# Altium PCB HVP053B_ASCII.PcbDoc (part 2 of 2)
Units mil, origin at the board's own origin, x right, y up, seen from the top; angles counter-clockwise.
Board outline 3600 x 3000 mil, 4 copper layers (Top Layer, Signal Layer 1, Signal Layer 2, Bottom Layer), stack 39.6 mil thick; 143 components, 62 nets, 279 pads, 97 vias.
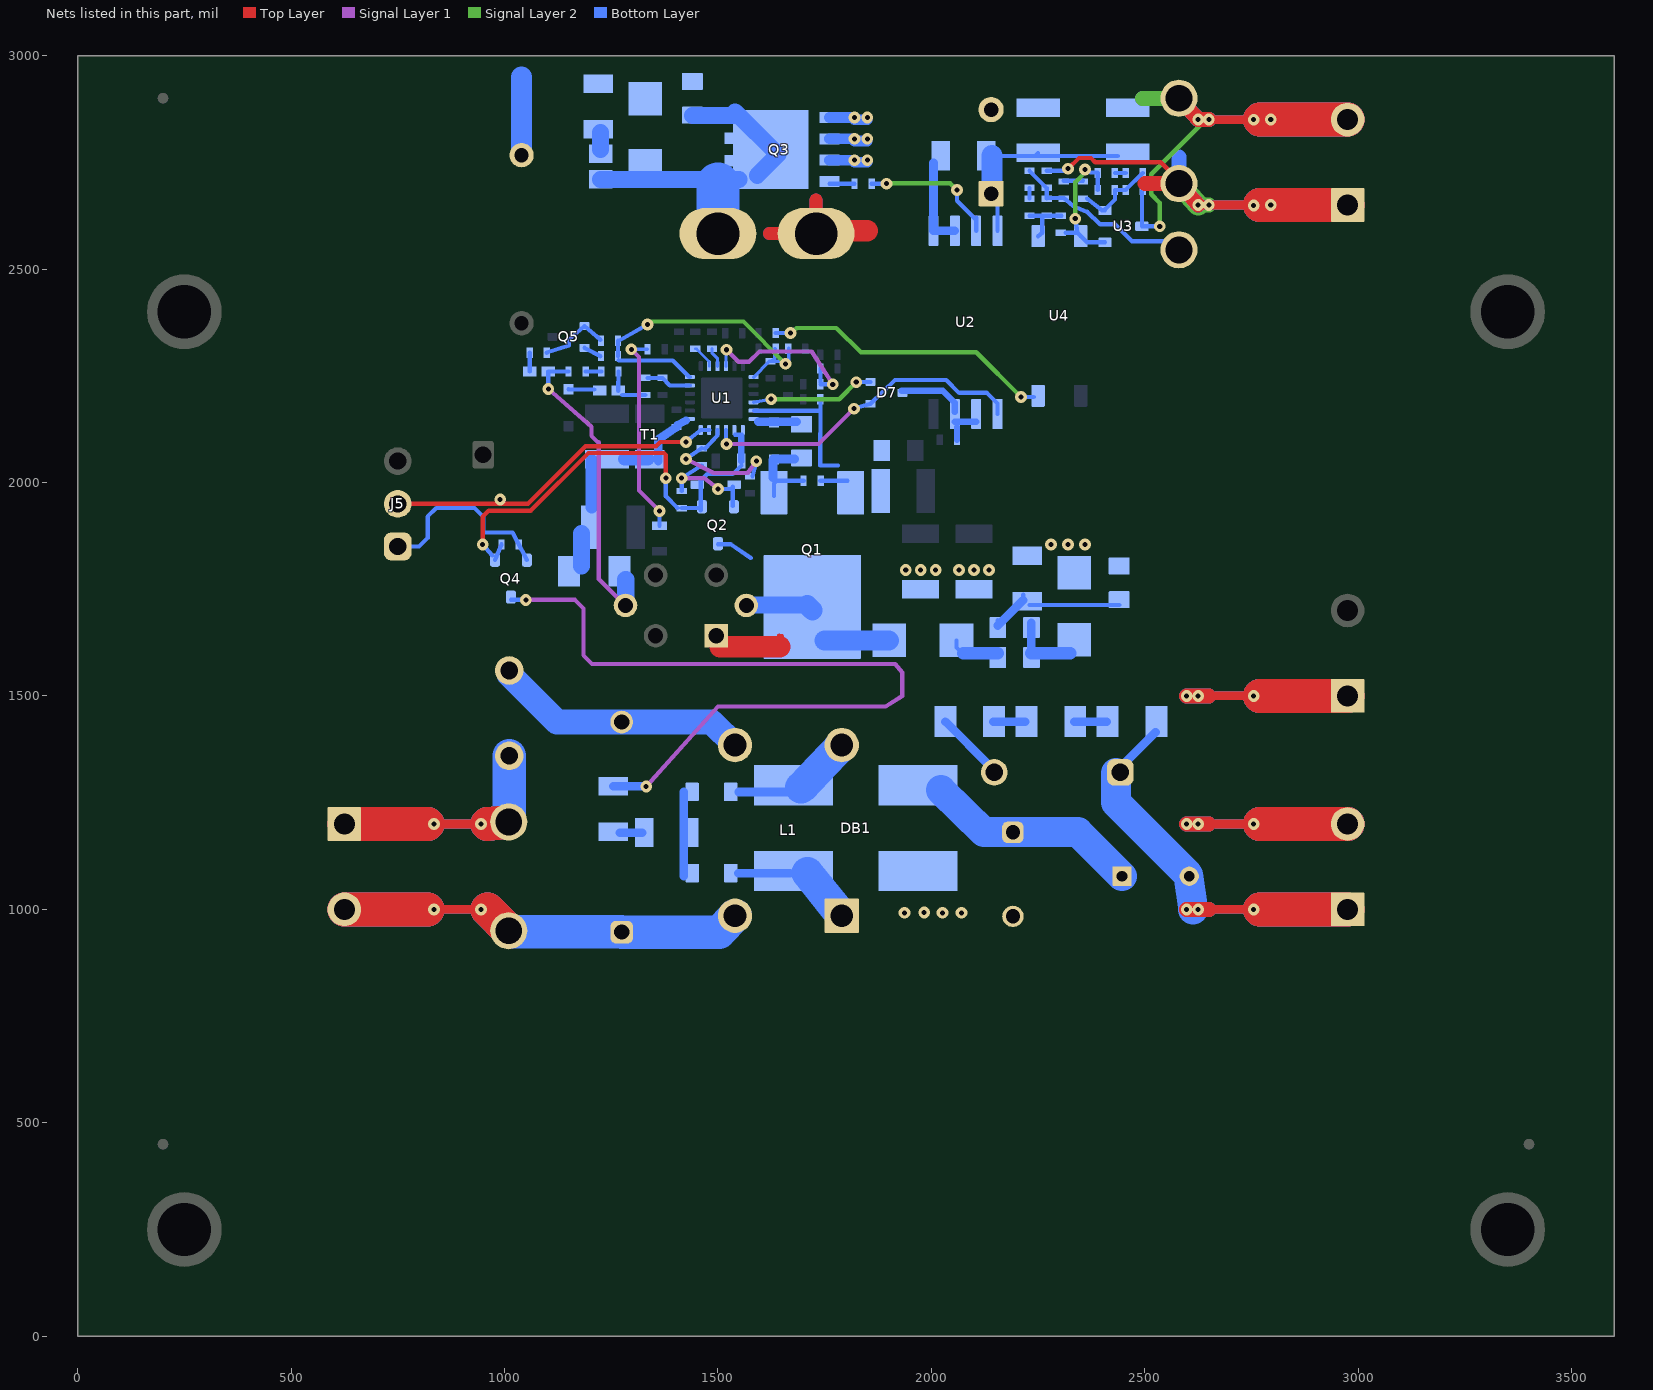
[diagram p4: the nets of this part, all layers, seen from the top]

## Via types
v1: diameter 27.56, hole 11.81, Top Layer to Bottom Layer, tented top, 38 vias
v2: diameter 27.56, hole 11.81, Top Layer to Bottom Layer, tented both sides, 34 vias
v3: diameter 27.56, hole 11.81, Top Layer to Bottom Layer, 20 vias
v4: diameter 19.68, hole 7.87, Top Layer to Bottom Layer, 5 vias

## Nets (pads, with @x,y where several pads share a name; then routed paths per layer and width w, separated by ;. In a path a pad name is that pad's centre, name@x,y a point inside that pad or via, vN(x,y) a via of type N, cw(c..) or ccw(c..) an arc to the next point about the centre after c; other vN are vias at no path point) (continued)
GND_P0: C1.2 C2.2 DB1.4 J2.2 R35.1 | length 1645.6
  Top Layer w20: v1@2630,1200 2770,1200
  Top Layer w35: v1(2598,1200) 2650,1200
  Top Layer w80: 2770,1200 J2.2@2975,1200
  Signal Layer 1 w20: v1@2630,1200 2770,1200
  Signal Layer 1 w80: 2770,1200 J2.2@2975,1200
  Signal Layer 2 w20: v1@2630,1200 2770,1200
  Signal Layer 2 w80: 2770,1200 J2.2@2975,1200
  Bottom Layer w10: C2.2@2137.66,1321.77 C2.2@2137.66,1335.25
  Bottom Layer w20: R35.1@2032.91,1440 C2.2@2137.66,1335.25 ; v1@2630,1200 2770,1200
  Bottom Layer w35: v1(2598,1200) 2650,1199.77
  Bottom Layer w80: 2770,1200 J2.2@2975,1200
  other v1: 1936.75,992.02 2026.32,992.02 2070.71,992.02 1983.18,992.75 2625,1200
  other v3: 2755,1200
GND_S: C7.2 C8.2 C9.2 C16.2 C20.1 C26.2 D10.2 J4.2 Q3.1 Q3.2 Q3.3 R12.1 R31.2 TP3.1 U2.5 U2.6 U3.3 | length 2959
  Top Layer w20: v3(2650,2850) 2770,2850
  Top Layer w35: TP3.1@2580,2900 v3(2625,2850) v3(2650,2850)
  Top Layer w80: 2770,2850 v3(2795,2850) J4.2@2975,2850
  Signal Layer 1 w20: v3(2650,2850) 2770,2850
  Signal Layer 1 w35: TP3.1@2580,2900 v3(2625,2850) v3(2650,2850)
  Signal Layer 1 w80: 2770,2850 v3(2795,2850) J4.2@2975,2850
  Signal Layer 2 w10: v2(2535,2600) 2535,2655 2515,2675 2515,2722 v3@2641.5,2848.5
  Signal Layer 2 w20: v3(2650,2850) 2770,2850
  Signal Layer 2 w35: 2495,2900 TP3.1@2580,2900 v3(2625,2850) v3(2650,2850)
  Signal Layer 2 w80: 2770,2850 v3(2795,2850) J4.2@2975,2850
  Bottom Layer w10: R31.2@2495,2685 2493.31,2683.31 U3.3@2493.31,2600 v2(2535,2600)
  Bottom Layer w20: C8.2@2005,2748.43 U2.5@2005,2589.57 U2.6@2055,2589.57 ; v3(2650,2850) 2770,2850
  Bottom Layer w25: Q3.3@1761.22,2755 v1(1820,2755) ; Q3.2@1761.22,2805 v1(1820,2805) ; Q3.1@1761.22,2855 v1(1820,2855) ; v1@1820,2750 v1@1850,2750 ; v1@1820,2800 v1@1850,2800 ; v1@1820,2850 v1@1850,2850 ; v3(2625,2850) v3(2650,2850)
  Bottom Layer w35: 2495,2900 TP3.1@2580,2900 v3(2625,2850) v3(2650,2850)
  Bottom Layer w50: C20.1@1040,2766.85 1040,2950
  Bottom Layer w80: 2770,2850 v3(2795,2850) J4.2@2975,2850
  other v1: 1850,2755 1850,2805 1850,2855
  other v3: 2755,2849.81
IPC: R6.1 R17.2 U1.4 | length 418
  Signal Layer 1 w10: v2(1519.8,2310.91) 1548,2283 1572.52,2283 1597.27,2307 1719,2307 v2(1769,2230)
  Bottom Layer w7.87: U1.4@1518.81,2272.53 1518.81,2309.92 v2(1519.8,2310.91)
  Bottom Layer w10: R6.1@1740,2230 v2@1775,2230 ; R6.1@1740,2235 R17.2@1740,2267
NetC1_1: C1.1 DB1.1 L2.1 | length 507
  Bottom Layer w70: DB1.1@2022.69,1279.42 2122.91,1180.99 2190.68,1180.99 2343.24,1180.99 L2.1@2446.59,1077.65
NetC3_1: C3.1 J1.2 L1.2 TP2.1 | length 2169.5
  Top Layer w20: 820,1000 960,1000
  Top Layer w80: J1.2@625,1000 820,1000 ; 960,1000 TP2.1@1010,950
  Signal Layer 1 w20: 820,1000 960,1000
  Signal Layer 1 w80: J1.2@625,1000 820,1000 ; 960,1000 TP2.1@1010,950
  Signal Layer 2 w20: 820,1000 960,1000
  Signal Layer 2 w80: J1.2@625,1000 820,1000 ; 960,1000 TP2.1@1010,950
  Bottom Layer w10: TP2.1@1007.28,947.72 TP2.1@1013.52,947.72
  Bottom Layer w20: 820,1000 960,1000
  Bottom Layer w78.74: TP2.1@1013.52,947.72 1273.59,947.72 C3.1@1274.58,946.74 1500,946.74 ; 1502.5,946.74 L1.2@1540,985
  Bottom Layer w80: J1.2@625,1000 820,1000 ; 960,1000 TP2.1@1010,950
  other v3: 835,1000 945,1000
NetC3_2: C3.2 F1.1 L1.3 | length 606
  Bottom Layer w59.06: F1.1@1011.02,1559.54 1011.02,1550.91 1123.06,1438.87 C3.2@1274.58,1438.87 1485,1438.87 L1.3@1540,1385
NetC6_2: C6.2 R2.1 R5.2 | length 302.6
  Bottom Layer w10: R5.2@2155.63,1675 R5.2@2155.63,1677.48 ; C6.2@2215,1730.72 C6.2@2215,1736.85 ; C6.2@2230,1712.75 R2.1@2440,1712.75
  Bottom Layer w20: R5.2@2155.63,1665 C6.2@2215,1724.37
NetC11_1: C11.1 D7.3 U2.2 U2.3 | length 238.6
  Bottom Layer w15: D7.3@1930,2215 1960,2215 2027,2215 2055,2186.94 U2.3@2055,2165 ; U2.3@2055,2142 U2.2@2105,2142 ; C11.1@2060,2100 U2.3@2060,2130
NetC15_1: C15.1 R12.2 | length 40
  Bottom Layer w39.37: C15.1@1225,2780 R12.2@1225,2820
NetC15_2: C15.2 C16.1 D10.1 Q3.5 Q3.6 Q3.7 Q3.8 Q3.9 T1.B | length 762.8
  Bottom Layer w39.37: C15.2@1225,2710 Q3.9@1550,2710 ; C16.1@1440,2860 Q3.9@1550,2860 ; Q3.9@1539.77,2868.47 1640.44,2767.8 Q3.9@1592.02,2719.38
  Bottom Layer w100: T1.B@1500,2583 1500,2700
NetC25_1: C25.1 R27.2 | length 25
  Bottom Layer w10: R27.2@2230,2665 C25.1@2230,2690
NetC27_1: C27.1 R29.1 | length 25
  Bottom Layer w10: C27.1@2430,2725 R29.1@2455,2725
NetC27_2: C27.2 C28.1 R32.1 U3.1 U4.3 | length 331
  Signal Layer 2 w10: v2(2337,2618) 2337.09,2703 2360,2725.91 v2(2360,2733)
  Bottom Layer w10: R32.1@2315,2585 U4.3@2342.01,2585 ; v2(2337,2618) U4.3@2342.01,2585 ; v2(2360,2733) 2373.02,2725.91 2389.09,2725.91 C27.2@2390,2725 C28.1@2390,2685 ; U3.1@2406.69,2562.6 2364.41,2562.6 U4.3@2350,2577.01 U4.3@2342.01,2585
NetC28_2: C28.2 R25.1 R29.2 R31.1 U3.2 | length 190.1
  Bottom Layer w10: R25.1@2365,2665 2399.71,2637.4 U3.2@2406.69,2637.4 2406.69,2639.82 2430,2663.13 C28.2@2430,2685 R31.1@2455,2685 R29.2@2495,2725
NetD1_1: D1.1 D2.1 R3.1 | length 197.4
  Bottom Layer w20: 1420,1077.65 1420.34,1275
NetD1_2: D1.2 DB1.3 L1.1 | length 250.6
  Bottom Layer w20: 1547.35,1085 DB1.3@1669.85,1085
  Bottom Layer w75: DB1.3@1710,1085 L1.1@1790,985
NetD2_2: D2.2 DB1.2 L1.4 | length 258.9
  Bottom Layer w20: 1549.28,1275 DB1.2@1670.28,1275
  Bottom Layer w75: DB1.2@1695,1285 L1.4@1790,1385
NetD5_2: D5.2 Q1.1 R15.2 R16.2 | length 194.2
  Bottom Layer w10: Q1.1@1631.43,1968.39 1631.43,1998.29 1636.97,2003.83 R16.2@1700.72,2003.83
  Bottom Layer w20: Q1.1@1629,2011 D5.2@1629,2053.69 ; D5.2@1630,2055 R15.2@1680,2055
NetD6_1: D6.1 Q2.2 R18.2 R24.1 | length 259.4
  Signal Layer 1 w10: v2(1415,2010) 1468.25,2010 v2(1500,1985)
  Bottom Layer w10: R24.1@1415,1980 v2(1415,2010) R18.2@1462,2040 ; v2(1500,1985) 1535,1985 ; Q2.2@1535,1945 D6.1@1535,1990
NetD8_1: D8.1 R7.1 | length 102.1
  Bottom Layer w10: D8.1@2058.74,1630 2058.74,1613.64 D8.1@2062.38,1610
  Bottom Layer w30: D8.1@2075,1600 R7.1@2155.63,1600
NetD9_1: D9.1 R5.1 R7.2 | length 161.5
  Bottom Layer w20: R7.2@2234.37,1600 R5.1@2234.37,1670.83
  Bottom Layer w30: R7.2@2234.37,1600 D9.1@2325,1600
NetD11_1: D11.1 R20.1 R38.2 | length 99
  Bottom Layer w10: D11.1@1266.65,2215 R38.2@1267,2260 ; D11.1@1276,2205 R20.1@1330,2205
NetD11_2: D11.2 D12.2 | length 60
  Bottom Layer w10: D12.2@1150,2218.31 D11.2@1210,2218
NetD13_1: D13.1 R41.2 | length 44
  Bottom Layer w10: R41.2@1059,2304 D13.1@1059.35,2260
NetF1_2: F1.2 J1.1 TP1.1 | length 1696.5
  Top Layer w20: 820,1200 960,1200
  Top Layer w80: J1.1@625,1200 820,1200 ; 960,1200 TP1.1@1010,1205
  Signal Layer 1 w20: 820,1200 960,1200
  Signal Layer 1 w80: J1.1@625,1200 820,1200 ; 960,1200 TP1.1@1010,1205
  Signal Layer 2 w20: 820,1200 960,1200
  Signal Layer 2 w80: J1.1@625,1200 820,1200 ; 960,1200 TP1.1@1010,1205
  Bottom Layer w20: 820,1200 960,1200
  Bottom Layer w78.74: TP1.1@1009.58,1204.61 1011.02,1206.05 F1.2@1011.02,1359.54
  Bottom Layer w80: J1.1@625,1200 820,1200 ; 960,1200 TP1.1@1010,1205
  other v3: 835,1200 945,1200
NetJ5_1: J5.1 Q4.2 R10.1 | length 453.7
  Bottom Layer w10: J5.1@750,1850 800,1850 820,1870 820,1920 840,1940 930,1940 950,1920 950,1883 1019,1883 Q4.2@1052.4,1818.31
NetQ3_4: Q3.4 R11.2 | length 58.8
  Bottom Layer w10: Q3.4@1761.22,2700 R11.2@1820,2700
NetQ4_3: Q4.3 R4.2 | length 1875.3
  Signal Layer 1 w10: v2(1050,1725) 1165,1725 1185,1705 1185,1595 1205,1575 1915,1575 1931.97,1555 1931.97,1500 1892.39,1475 1500,1475 v2(1332,1288.15)
  Bottom Layer w10: Q4.3@1015,1725 v2(1050,1725)
  Bottom Layer w20: R4.2@1255,1288.15 v2(1332,1288.15)
NetQ5_1: Q5.1 R40.2 R41.1 | length 166.2
  Bottom Layer w10: R41.1@1099,2304 1150.94,2321 1150.94,2335 Q5.1@1187.42,2366.59 R40.2@1224.37,2334
NetQ5_2: Q5.2 R39.2 | length 41.7
  Bottom Layer w10: Q5.2@1187.42,2315.41 R39.2@1224.37,2296
NetR3_2: R3.2 R4.1 | length 53.2
  Bottom Layer w20: R4.1@1269.67,1180 R3.2@1322.91,1180
NetR25_2: R25.2 R36.2 | length 45.1
  Bottom Layer w10: R36.2@2309.88,2706.59 R25.2@2355,2706.59
NetR26_1: R26.1 R27.1 R32.2 U4.1 | length 127.8
  Bottom Layer w10: R27.1@2230,2625 R26.1@2270,2625 R32.2@2305,2625 ; U4.1@2250,2577.01 2260,2585 R26.1@2260,2625
NetR33_1: R33.1 R34.2 | length 75.6
  Bottom Layer w20: R34.2@2335,1440 R33.1@2410.55,1440
NetR34_1: R34.1 R35.2 | length 75
  Bottom Layer w20: R35.2@2145,1440 R34.1@2220,1440
NetR37_2: R37.2 R38.1 | length 37
  Bottom Layer w10: R37.2@1190,2260 R38.1@1227,2260
OPTO_C: R30.2 U4.6 | length 676
  Signal Layer 2 w10: v2(1670,2350) 1685,2362 1777,2362 1835,2305 2105,2305 v1(2210,2200)
  Bottom Layer w10: R30.2@1635,2350 v2(1670,2350) ; v1(2210,2200) U4.6@2240,2200
P13: C23.1 D6.2 Q2.1 Q4.1 R10.2 R24.2 U1.13 U1.14 | length 1064.7
  Top Layer w10: v2@949.01,1850 949,1920 963,1934 1061.63,1934 1196.63,2069 1373.5,2069 1378,2064.5 v2(1378,2010)
  Bottom Layer w10: v2(949,1855) Q4.1@971.51,1829 ; Q4.1@977.6,1818.31 R10.2@993,1855 ; v2(1378,2010) 1378,1968 R24.2@1405,1940 ; R24.2@1415,1940 Q2.1@1452.77,1940 ; Q2.1@1460,1935 1460,2005 1475,2020 1535,2020 C23.1@1555,2040 ; U1.14@1540,2112 U1.13@1556.22,2111.97
  Bottom Layer w15: C23.1@1555,2050 1555,2109
PWML: D5.1 R15.1 U1.12 | length 90
  Bottom Layer w20: 1595,2142 R15.1@1685,2142
QLSRC: Q1.3 R16.1 R19.2 R21.2 R28.1 U1.11 | length 414.8
  Bottom Layer w10: U1.11@1585,2168 1740,2168 ; R16.1@1739.97,2003.83 Q1.3@1803.72,2003.83 ; R19.2@1740,2195 1739.97,2040 1781,2040
RDM: R9.2 U1.3 | length 45.8
  Bottom Layer w7.87: R9.2@1485.96,2312.88 1485.96,2303.52 1499.12,2290.36 U1.3@1499.12,2272.53
REF: C12.1 C14.1 R14.1 R39.1 R40.1 U1.7 U1.24 | length 839.7
  Signal Layer 2 w9.84: 1560,2377 v2(1658,2278) ; v2@1659.44,2269.49 v2@1664.53,2274.58
  Signal Layer 2 w10: v2@1340,2377 1560,2377
  Bottom Layer w8: U1.7@1583.77,2246.94 1620.5,2283.67 C12.1@1624.99,2283.67 ; C14.1@1634.9,2312.88 1632.61,2312.88 1632.61,2291.29 C12.1@1624.99,2283.67 ; R14.1@1665.76,2314.85 1665.76,2275.81 1664.53,2274.58 1655.44,2283.67 C12.1@1624.99,2283.67
  Bottom Layer w9.84: U1.24@1432.72,2246.94 U1.24@1434.16,2246.94
  Bottom Layer w10: R39.1@1266,2296 R40.1@1266,2332 ; R40.1@1266,2331 v2(1335,2370) ; R39.1@1267.65,2286 1394,2286 U1.24@1432.72,2246.94
RT1_1: R1.1 RT1.1 | length 487.6
  Signal Layer 1 w9.84: v2(1297,2312) 1315,2294 ; v2@1297.34,2310.91 v2@1306.49,2310.91
  Signal Layer 1 w10: 1315,2294 1315,1981 v2(1363,1933)
  Bottom Layer w8: v2(1297,2312) R1.1@1335,2312
  Bottom Layer w10: RT1.1@1362.93,1898.9 v2(1363,1933)
RTZ: R8.2 U1.2 | length 56
  Bottom Layer w6: R8.2@1446.59,2312.88 1450.15,2312.88 1479.44,2283.59 U1.2@1479.44,2272.53
RUN: D7.2 U1.10 | length 301.1
  Signal Layer 2 w9.84: v2(1624.74,2195.03) 1784,2195
  Signal Layer 2 w10: 1784,2195.03 v2(1824,2235)
  Bottom Layer w7.87: U1.10@1583.77,2187.88 v2(1624.74,2195.03) v2@1617.59,2187.88
  Bottom Layer w10: v2(1824,2235) D7.2@1857.6,2235.59
SR_DRV: R11.1 U2.7 | length 325.9
  Signal Layer 2 w10: v2(1895,2700) 1895.7,2700.7 2044.3,2700.7 v2(2060,2685)
  Bottom Layer w10: R11.1@1860,2700 v2(1895,2700) ; v2(2060,2685) 2060,2660 U2.7@2105,2615 ; U2.7@2105,2589.57 U2.7@2105,2620
SRDRV: D7.1 U1.15 U2.1 | length 773.7
  Signal Layer 1 w10: v2(1520,2090) 1735.67,2090 v2(1818.64,2172.96)
  Bottom Layer w10: v2@1519,2090 U1.15@1519,2123 ; v2(1818.64,2172.96) D7.1@1857.6,2184.41 1915,2240 2035,2240 2065,2210 2130,2210 U2.1@2155,2185 ; U2.1@2155,2160.43 U2.1@2155,2184.84
SWS: C24.2 R18.1 U1.16 | length 324.3
  Signal Layer 1 w10: v2(1425,2055) 1490,2022 1570,2022 v2(1590,2050)
  Bottom Layer w10: v2(1425,2055) R18.1@1462,2080 ; R18.1@1470,2079.04 1499.2,2110 U1.16@1499.12,2122.92 ; C24.2@1580.79,2014.3 v2(1590,2050)
Vaux: D3.2 D13.2 R37.1 T1.6 | length 745.1
  Signal Layer 1 w10: v2(1102.65,2219) 1204,2130.77 1204,2109.23 1219.23,2094 1221,2094 1221,1774 T1.6@1290,1705
  Bottom Layer w10: v2(1102.65,2219) D13.2@1102.65,2260 R37.1@1150,2260
  Bottom Layer w40: T1.6@1284,1713 D3.2@1284,1773
Vbulk: C4.2 C5.2 C6.1 D9.2 J3.1 R2.2 T1.1 | length 1735.3
  Top Layer w10: 1643.41,1641.75 1645.16,1640 1650,1640
  Top Layer w20: v3@2630,1500 2770,1500
  Top Layer w35: v3(2598,1500) 2650,1500
  Top Layer w50: T1.1@1505,1615 1645,1615
  Top Layer w80: 2770,1500 J3.1@2975,1500
  Signal Layer 1 w20: v3@2630,1500 2770,1500
  Signal Layer 1 w25: v3(2598,1500) 2650,1500
  Signal Layer 1 w80: 2770,1500 J3.1@2975,1500
  Signal Layer 2 w20: v3@2630,1500 2770,1500
  Signal Layer 2 w25: v3(2598,1500) 2650,1500
  Signal Layer 2 w80: 2770,1500 J3.1@2975,1500
  Bottom Layer w20: v3@2630,1500 2770,1500
  Bottom Layer w35: v3(2598,1500) 2650,1500
  Bottom Layer w80: 2770,1500 J3.1@2975,1500
  other v1: 1940,1795 1975,1795 2010,1795 2065,1795 2100,1795 2135,1795 2280,1855 2320,1855 2360,1855
  other v3: 2625,1500 2755,1500
Vbulk0: C2.1 J2.1 L2.2 R33.2 | length 2112.7
  Top Layer w20: v1@2630,1000 v3(2755,1000) 2770,1000
  Top Layer w35: v1(2598,1000) 2650,1000
  Top Layer w80: 2770,1000 J2.1@2975,1000
  Signal Layer 1 w20: v1@2630,1000 v3(2755,1000) 2770,1000
  Signal Layer 1 w35: v1@2598,999.77 2650,999.77
  Signal Layer 1 w80: 2770,1000 J2.1@2975,1000
  Signal Layer 2 w20: v1@2630,1000 v3(2755,1000) 2770,1000
  Signal Layer 2 w35: v1(2598,1000) 2650,1000
  Signal Layer 2 w80: 2770,1000 J2.1@2975,1000
  Bottom Layer w20: C2.1@2430,1320 R33.2@2525,1415 ; v1@2630,1000 v3(2755,1000) 2770,1000
  Bottom Layer w35: v1@2598,999.77 2650,999.77
  Bottom Layer w70: C2.1@2432.81,1319.77 2432.91,1250 2601.59,1080.99 v1@2613,1000
  Bottom Layer w80: 2770,1000 J2.1@2975,1000
  other v1: 2625,1000
VDD: C10.1 C17.1 C18.2 C22.2 D3.1 U1.19 | length 363
  Bottom Layer w18: C17.1@1405,2135 U1.19@1425,2145
  Bottom Layer w20: C10.1@1360,2050 1360,2100 C17.1@1403,2130
  Bottom Layer w30: C22.2@1204.46,1941.82 C18.2@1205,2050 ; C18.2@1281.04,2054.85 C10.1@1336.04,2054.85
  Bottom Layer w40: 1180,1805 C22.2@1180,1880
VOUT: C7.1 C8.1 C9.1 C26.1 J4.1 R22.1 T1.A TP4.1 U2.8 | length 3122
  Top Layer w10: v2(2320,2735) 2346,2760 2374,2760 2384,2750.05 2537.36,2750 2580,2706.97 TP4.1@2580,2700
  Top Layer w20: v3(2625,2650) v3(2650,2650) 2770,2650
  Top Layer w30: 1621.13,2583 T1.A@1651.13,2583 ; T1.A@1730,2632 1730,2662
  Top Layer w35: 2500,2700 TP4.1@2580,2700 v3(2625,2650)
  Top Layer w50: T1.A@1700,2590 1850,2590
  Top Layer w80: 2770,2650 v3(2795,2650) J4.1@2975,2650
  Signal Layer 1 w20: v3(2625,2650) v3(2650,2650) 2770,2650
  Signal Layer 1 w30: 1621.13,2583 T1.A@1651.13,2583 ; T1.A@1730,2632 1730,2662 ; T1.A@1809,2583 1839,2583
  Signal Layer 1 w35: 2505,2700 TP4.1@2580,2700 v3(2625,2650)
  Signal Layer 1 w39.37: T1.A@1676.91,2582.25 1686.43,2582.25 T1.A@1676.91,2591.78
  Signal Layer 1 w40: T1.A@1700,2590 T1.A@1775,2590
  Signal Layer 1 w80: 2770,2650 v3(2795,2650) J4.1@2975,2650
  Signal Layer 2 w20: v3(2650,2650) 2770,2650
  Signal Layer 2 w35: v3(2625,2650) v3(2650,2650)
  Signal Layer 2 w50: TP4.1@2580,2700 v3(2625,2650)
  Signal Layer 2 w80: 2770,2650 v3(2795,2650) J4.1@2975,2650
  Bottom Layer w10: C7.1@2141.93,2678.5 C7.1@2140,2676.57 2155,2661.57 U2.8@2155,2589.57 ; C8.1@2141.93,2765 C9.1@2243.15,2765 ; C9.1@2250,2771.85 C9.1@2243.15,2765 ; R22.1@2270,2730 2310,2730 v2(2320,2735) ; C26.1@2436.8,2765 C9.1@2243.15,2765
  Bottom Layer w20: v3(2650,2650) 2770,2650
  Bottom Layer w25: v3@2625.32,2650 v3(2650,2650)
  Bottom Layer w35: 2580,2762.93 TP4.1@2580,2700 v3(2625,2650)
  Bottom Layer w50: C7.1@2141.93,2678.5 C8.1@2141.93,2765
  Bottom Layer w80: 2770,2650 v3(2795,2650) J4.1@2975,2650
  other v3: 2755,2648.84
VOUT_A: C25.2 R22.2 R26.2 R36.1 TP5.1 | length 432.9
  Bottom Layer w10: C25.2@2230,2730 R22.2@2270,2690 R26.2@2270,2665 ; R26.2@2274.88,2666.59 2309.88,2666.59 2331.74,2648 2365,2634 2395.28,2605 2430,2605 2470,2565 2560,2565 TP5.1@2580,2545
VS: R20.2 R23.2 U1.23 | length 106.7
  Bottom Layer w10: R20.2@1335,2245 R23.2@1370,2245 1387,2227.25 U1.23@1434.16,2227.25
Vswn: D8.2 Q1.2 Q2.3 T1.2 | length 399.4
  Bottom Layer w7.87: Q1.2@1721.2,1700.68 Q1.2@1721.2,1708.55
  Bottom Layer w10: Q2.3@1500,1855 1530,1855 1577,1823
  Bottom Layer w40: T1.2@1571.5,1712.75 Q1.2@1709.12,1712.75
  Bottom Layer w47.24: Q1.2@1709.12,1712.75 Q1.2@1721.2,1700.68 ; Q1.2@1750,1630 D8.2@1900,1630
XCD: J5.2 U1.17 U1.18 | length 809.3
  Top Layer w10: J5.2@740,1950 1055,1950 1190,2085 1355,2085 1365,2095 v2(1425,2095)
  Bottom Layer w10: v2(1425,2095) U1.18@1459.75,2122.92 U1.17@1479.44,2122.92
  other v1: 990,1960
pads on no net: FID1.1 FID2.1 FID3.1 FID4.1 FID5.1 FID6.1 H1.1 H2.1 H3.1 H4.1 H5.0 H6.0 H7.0 H8.0 LBL1.0 SH-J1.0 T1.3 T1.5
copper on no net: | length 1.2
  Bottom Layer w12: 1344.22,1642.61 1345.08,1641.75

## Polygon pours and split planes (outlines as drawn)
GND_P on Bottom Layer "BOTTOM_LAYER_GND_P_P318" (solid, remove dead copper, pour order 318): 2592.05,2030 2592.05,1707.95 2619.98,1680.01 2645,1680.01 2645,2030
VOUT on Bottom Layer "BOTTOM_LAYER_VOUT_P314" (solid, remove dead copper, pour order 314): 2655,2820 2655,2630 2515,2630 2515,2755 2110,2755 2110,2820
Vbulk on Bottom Layer "BOTTOM_LAYER_VBULK_P308" (solid, remove dead copper, pour order 308): 1925,1815 1925,1765 2156,1765 2166,1775 2410.55,1775 2410.55,1890 2225,1890 2150,1815
GND_P on Bottom Layer "BOTTOM_LAYER_GND_P_P296" (solid, remove dead copper, pour order 296): 2525.51,1870 2598.51,1797 2634.79,1797 2635.32,1870 2635.32,2030 1950,2030 1950,1870
no net on Bottom Layer "BOTTOM_LAYER_NONET_P294" (solid, remove dead copper, pour order 294): 1052.4,2033.55
no net on Bottom Layer "BOTTOM_LAYER_NONET_P295" (solid, remove dead copper, pour order 295): 2050,2000
Vswn on Bottom Layer "BOTTOM_LAYER_VSWN_P297" (solid, remove dead copper, pour order 297): 1570,1830 1658,1830 1658,1750 1570,1750
Vswn on Bottom Layer "BOTTOM_LAYER_VSWN_P299" (solid, remove dead copper, pour order 299): 1570,1675 1665,1675 1665,1590 1570,1590
Vswn on Bottom Layer "BOTTOM_LAYER_VSWN_P300" (solid, remove dead copper, pour order 300): 1784.41,1830 1885,1830 1885,1680 1784.41,1680
NetC15_2 on Bottom Layer "Bottom Layer-NetC33_2" (solid, pour order 303): 1395,2660 1395,2900 1720,2900 1720,2660
GND_S on Bottom Layer "Bottom Layer-SGND" (solid, remove dead copper, pour order 307): 1000,2980 1000,2915 1795,2915 1795,2830 1795,2726.26 2050,2726.26 2050,2830 2655,2830 2655,2960 2635,2980
GND_P on Bottom Layer "BOTTOM_LAYER_GND_P_P306" (solid, remove dead copper, pour order 306): 1950,2150 1950,2020 2147.09,2020 2147.09,2150
QLSRC on Bottom Layer "BOTTOM_LAYER_QLSRC_P302" (solid, remove dead copper, pour order 302): 1770,2100 1770,1930 1890,1930 1890,2100
Vbulk on Bottom Layer "BOTTOM_LAYER_VBULK_P304" (solid, remove dead copper, pour order 304): 2512,1844 2645,1711 2645,1502 2397,1502 2397,1844
GND_P0 on Bottom Layer "BOTTOM_LAYER_GND_P0_P305" (solid, remove dead copper, pour order 305): 1900,1120 1900,880 2250,880 2250,1120
GND_S on Signal Layer 2 "Signal Layer 2-SGND" (solid, pour order 292): 949,2940.85 949,2790 1199,2540 2299,2540 2495,2540 2495,2725 2605,2835 2654,2835 2654,2915 2654,2965 2638.62,2980.38 988.08,2979.93
GND_P on Signal Layer 2 "SIGNAL_LAYER_2_GND_P_P293" (solid, remove dead copper, pour order 293): 1374.42,2365 1374.42,1541.23 2650,1541.23 2650,2143.51 2428.51,2365
GND_P on Signal Layer 2 "SIGNAL_LAYER_2_GND_P_P291" (solid, remove dead copper, pour order 291): 928,2390 928,1545.17 1765.07,1545.17 1769.08,2390
GND_P0 on Signal Layer 2 "SIGNAL_LAYER_2_GND_P0_P290" (solid, remove dead copper, pour order 290): 1900.33,1479.61 1900.33,880 2650,880 2650,1479.61
VOUT on Signal Layer 1 "Signal Layer 1-VN" (solid, pour order 288): 1155,2585 1185.01,2554.99 2589.99,2554.99 2655,2620 2655,2747 2432,2970 1155,2970
GND_P on Signal Layer 1 "SIGNAL_LAYER_1_GND_P_P289" (solid, remove dead copper, pour order 289): 1416.08,2301.91 1416.08,1540.41 2650,1540.41 2650,2301.91
GND_P on Signal Layer 1 "SIGNAL_LAYER_1_GND_P_P287" (solid, remove dead copper, pour order 287): 928,2389 928,1545.17 1781,1545.17 1781,2389
GND_P0 on Signal Layer 1 "SIGNAL_LAYER_1_GND_P0_P286" (solid, remove dead copper, pour order 286): 1900.33,1494 1900.33,880 2650,880 2650,1494
GND_P on Top Layer "TOP_LAYER_GND_P_P316" (solid, remove dead copper, pour order 316): 2550,2050 2550,1675 2645,1675 2645,2050
VOUT on Top Layer "Top Layer-VN" (solid, pour order 285): 1150,2975 1150,2730.42 1246.95,2660 1600,2660 1600,2555 2000,2555 2009.84,2564.84 2600.31,2565.31 2655,2620 2655,2745 2425,2975
GND_P on Top Layer "TOP_LAYER_GND_P_P283" (solid, remove dead copper, pour order 283): 1775,2226.84 1775,1850.06 2635.32,1849.92 2635.32,1964.68 2373.16,2226.84
GND_P on Top Layer "TOP_LAYER_GND_P_P284" (solid, remove dead copper, pour order 284): 940,2390 940,1887.57 1860,1887.57 1860,2390
Vbulk on Top Layer "TOP_LAYER_VBULK_P282" (solid, remove dead copper, pour order 282): 1579.94,1810 1579.94,1550 2450,1550 2450,1810
GND_P0 on Top Layer "TOP_LAYER_GND_P0_P280" (solid, remove dead copper, pour order 280): 1900,1495 1900,880 2250,880 2250,1495
Vbulk on Top Layer "TOP_LAYER_VBULK_P281" (solid, remove dead copper, pour order 281): 2225.7,1905 2225.7,1550 2450,1550 2450,1905

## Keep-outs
Top Layer:
  rectangle: 930.84,1654.42 961.35,1694.77
  lines w10: 1330,2245 1375,2245 ; 1387,2227.25 1435,2227.25
Signal Layer 1:
  rectangle: 930.84,1654.42 959.39,1694.77
  lines w10: 1335,2245 1375,2245 ; 1387,2227.25 1435,2227.25
Signal Layer 2:
  rectangle: 930.84,1654.42 958.4,1694.77
  lines w10: 1325,2245 1375,2245 ; 1387,2227.25 1435,2227.25
Bottom Layer:
  rectangle: 930.84,1654.42 961.35,1694.77
Keep-Out Layer:
  text ".Layer_Name" at 577,-858.49 h60

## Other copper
Top Layer:
  text ".Layer_Name" at 577,-858.49 h60
Bottom Layer:
  text ".Layer_Name" at 577,-858.49 h60

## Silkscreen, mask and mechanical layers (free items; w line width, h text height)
Top Overlay:
  region: 2460,235 2160,235 2160,135 2460,135
  lines w6: 1107.26,897.53 1441.9,897.53 1441.9,1488.08 1107.26,1488.08 1107.25,897.53
  lines w7: 950,1650 950,1710
  lines w7.87: 1148.49,2393.06 1148.49,2459.5
  lines w10: 645,1985 690,1960 ; 645,1985.83 645,2030 690,2050 ; 690,1850 645,1870 645,1917.69 690,1940 ; 1937,1411 2652,1411 ; 1937,1412 1937,1772 ; 1937,1816 1937,2462 2652,2462 2652,1413 ; 1945,1412 1945,1772 ; 1945,1816 1945,2462 ; 1954,1412 1954,1772 ; 1954,1816 1954,2462 ; 1962,1412 1962,1772 ; 1962,1816 1962,2462 ; 1970,1412 1970,1772 ; 1970,1816 1970,2462 ; 2135,1360 2135,1410 ; 2160,1360 2160,1410 ; 2430,1360 2430,1410 ; 2455,1360 2455,1410 ; 3155,1000 3205,1000 ; 3155,1200 3205,1200 ; 3155,1500 3205,1500 ; 3155,1700 3205,1700 ; 3155,2650 3205,2650 ; 3155,2850 3205,2850 ; 3180,975 3180,1025 ; 3180,1475 3180,1525 ; 3180,2625 3180,2675
  lines w30: 2055.47,2956.27 cw(c2140,2775) 2224.52,2956.27 ; 2107.25,902.57 ccw(c2191.77,1083.83) 2276.3,902.57
  text "GND_S" at 2310,2915 h40
  text "DC Output" at 3190,2900 h90
  text "15V 4A" at 3270,2780 h90
  text "CAUTION" at 120,2710 h100
  text "B" at 1487,2660 h40
  text "A" at 1717,2660 h40
  text "VOUT" at 2350,2645 h40
  text "HOT SURFACE" at 125,2614.57 h100
  text "Jumper:" at 290,2105 h40
  text "3" at 820,2030.1 h40
  text "XCD DISABLED" at 168,2010 h40
  text "2" at 820,1931 h40
  text "XCD ENABLED" at 200,1850 h40
  text "1" at 824,1831 h40
  text "40VDC" at 3387,1497 h90 r90
  text "to 500VDC" at 3462,1437 h90 r90
  text "J3: DC Input" at 3292,1412 h90 r90
  text "+" at 2340,1270 h60
  text "LINE" at 307.73,1180 h40
  text "LINE" at 938.17,1089 h35
  text "NEUT" at 937.73,1030 h35
  text "NEUT" at 307.73,980 h40
  text "Output" at 3376,960 h90 r90
  text "Rectified-AC" at 3296,880 h90 r90
  text "J1: AC Input" at 250,820 h90
  text "90VAC to 264VAC" at 150,735 h90
  text "50/60 Hz" at 295,650 h90
  text "DANGER HIGH VOLTAGE" at 2490,640 h100
  text "DANGER HIGH VOLTAGE" at 45,555 h100
  text "CAUTION READ USER GUIDE FIRST" at 1600,420 h108.27
  text "UCC28781EVM-053" at 1500,250 h120
  text "HVP053  Rev. B" at 1500,150 h90
  text ".Layer_Name" at 577,-858.49 h60
Bottom Overlay:
  lines w5: 1316,2389 1315.5,2292 1325,2262 ; 1402,1993 1432,1993 ; 1412.17,2075 1441.83,2075 ; 1588.78,2399 1597,2372 ; 1638.09,2287.18 1650,2295 1650,2360 1639.83,2376 ; 1667,2034 1677,1986 ; 1719,2249 1719,2351 ; 1775.98,2318.91 1803,2340 ; 1790,2281 1814,2304 ; 2287,2678 2298.88,2739 ; 2289,2729 2316.67,2757 ; 2300.5,2569 2316.78,2548 2383,2548 2399.37,2529 ; 2329,2706.59 2351.39,2759 ; 2370,2713 2383,2750.05 2383,2836 ; 2395,2745 2395,2910 ; 2510,2725 2535,2745 ; 2511,2679 2530,2661
  lines w7: 1422,2265 1422,2284 ; 1422,2285 1442,2285
  lines w7.87: 1613.91,1351.81 1750,1352
  lines w8: 2355,1320 2385,1320 ; 2370,1305 2370,1335
  lines w10: 3035,1000 3085,1000 ; 3035,1200 3085,1200 ; 3035,1500 3085,1500 ; 3035,1700 3085,1700 ; 3035,2650 3085,2650 ; 3035,2850 3085,2850 ; 3060,975 3060,1025 ; 3060,1475 3060,1525 ; 3060,2625 3060,2675
  text "GND_S" at 2930,2780 h40
  text "CAUTION" at 801,2659 h100
  text "VOUT" at 2915,2580 h40
  text "HOT SURFACE" at 799,2568 h100
  text "B" at 1387,2560 h40
  text "A" at 1870,2560 h40
  text "CAUTION" at 3400,2100 h100
  text "HOT SURFACE" at 3405,2010 h100
  text "GND_P" at 2930,1630 h40
  text "Vbulk" at 2920,1430 h40
  text "DANGER" at 774,1372 h100
  text "HIGH VOLTAGE" at 773,1286 h100
  text "L" at 1111,1169 h100
  text "TP1" at 1110,1110 h72.83
  text "TP2" at 1110,1000 h72.83
  text "N" at 1120,916 h100
  text "DANGER" at 3500,850 h100
  text "HIGH VOLTAGE" at 3500,750 h100
  text "UCC28781EVM-053" at 3065,450 h108.27
  text "CAUTION" at 1405,260 h108.27
  text "READ USER GUIDE FIRST" at 1800,170 h108.27
  text ".Layer_Name" at 577,-858.49 h60
Top Paste:
  text ".Layer_Name" at 577,-858.49 h60
Bottom Paste:
  text ".Layer_Name" at 577,-858.49 h60
Top Solder:
  text ".Layer_Name" at 577,-858.49 h60
  text ".Layer_Name" at 577,-858.49 h60
Bottom Solder:
  text ".Layer_Name" at 577,-858.49 h60
Drill Guide:
  text ".Layer_Name" at 577,-858.49 h60
M1 Board Outline:
  drawing of 344 lines, arcs and shapes, not listed
  text ".Layer_Name" at 577,-858.49 h60
M2 Board Dimensions:
  rectangle: 125,-400 500,-275
  rectangle: 0,-275 125,-150
  lines w7: 0,-275 1000,-275 ; 125,-400 125,-150 ; 250,-400 250,-150 ; 500,-400 500,-150 ; 750,-400 750,-150 ; 0,-400 0,-150 1000,-150 1000,-400 0,-400
  text ".Layer_Name" at 577,-858.49 h60
M3 3D STEP Top:
  text ".Layer_Name" at 577,-858.49 h60
M4 3D STEP Bottom:
  text ".Layer_Name" at 577,-858.49 h60
M5 Assembly Top:
  lines w10: -292,-930.17 6308,-930.17 ; -292,-726.83 6310,-726.83 ; -292,-523.5 -292,-1133.5 3713,-1133.5 6310,-1133.5 6310,-523.5 -291.5,-523.5 -291.5,-1133.5 1284,-1133.5 ; 2173,-1133.5 2173,-523.5 ; 3440,-726.83 3440,-523.5 ; 4280,-726.83 4280,-523.5 ; 4902,-1140 4902,-937.17
  text "COMPONENTS MARKED 'DNP' SHOULD NOT BE POPULATED." at 1153.5,-318.5 h60
  text "ASSEMBLY VARIANT:" at 1153,-434 h60
  text ".VariantName" at 2189,-434 h60
  text "PCB VIEWED FROM TOP SIDE" at -228.5,-655.67 h60
  text "BOARD #:" at 2248,-655.67 h60
  text ".PRJ_Number" at 2793.5,-655.67 h60
  text "REV:" at 3638,-655.67 h60
  text ".PCB_Rev" at 3929.5,-655.67 h60
  text "SVN REV:" at 4476,-655.67 h60
  text ".VersionControl_RevNumber" at 4982,-655.67 h60
  text "TID #:" at 2248,-859 h60
  text ".TID" at 2793.5,-859 h60
  text "PLOT NAME =" at -228.5,-1064.34 h60
  text ".plot_File_Name" at 577,-1064.34 h60
  text "GENERATED    :" at 2250,-1064.34 h60
  text ".Print_Date" at 3119.5,-1064.34 h60
  text ".Print_Time" at 3848.5,-1064.34 h60
  text "TEXAS INSTRUMENTS" at 5113,-1064.34 h60
M6 Assembly Bottom:
  lines w10: -292.5,-727.33 6309.5,-727.33 ; -290.5,-930.67 6309.5,-930.67 ; 1115.5,-1140.5 1115.5,-937.67 ; 1737.5,-727.33 1737.5,-524 ; 2577.5,-727.33 2577.5,-524 ; 3844.5,-1134 3844.5,-524 ; 4733.5,-1134 6309,-1134 6309,-524 -292.5,-524 -292.5,-1134 2304.5,-1134 6309.5,-1134 6309.5,-524
  text "COMPONENTS MARKED 'DNP' SHOULD NOT BE POPULATED." at 6102,-318 h60
  text ".VariantName" at 5058,-434 h60
  text "ASSEMBLY VARIANT:" at 6097,-434 h60
  text ".VersionControl_RevNumber" at 1035.5,-656.17 h60
  text "SVN REV:" at 1541.5,-656.17 h60
  text ".PCB_Rev" at 2088,-656.17 h60
  text "REV:" at 2379.5,-656.17 h60
  text ".PRJ_Number" at 3224,-656.17 h60
  text "BOARD #:" at 3769.5,-656.17 h60
  text "PCB VIEWED FROM BOTTOM SIDE" at 6246,-656.17 h60
  text ".TID" at 3224,-859.5 h60
  text "TID #:" at 3769.5,-859.5 h60
  text "TEXAS INSTRUMENTS" at 904.5,-1064.84 h60
  text ".Print_Time" at 2169,-1064.84 h60
  text ".Print_Date" at 2898,-1064.84 h60
  text "GENERATED    :" at 3767.5,-1064.84 h60
  text ".plot_File_Name" at 5440.5,-1064.84 h60
  text "PLOT NAME =" at 6246,-1064.84 h60
M9 Title Sheet:
  lines w10: -491.5,1041.5 -291.5,1041.5 ; -491.5,3416.5 -291.5,3416.5 ; -491.5,5791.5 -291.5,5791.5 ; 2008.5,-1333.5 2008.5,-1133.5 ; 2008.5,7966.5 2008.5,8166.5 ; 4508.5,-1333.5 4508.5,-1133.5 ; 4508.5,7966.5 4508.5,8166.5 ; 6321,-1133.5 6321,-523.5 11303.5,-523.5 ; 7008.5,-1333.5 7008.5,-1133.5 ; 7008.5,7966.5 7008.5,8166.5 ; 9508.5,-1333.5 9508.5,-1133.5 ; 9508.5,7966.5 9508.5,8166.5 ; 11303.5,-1133.5 11303.5,-523.5 ; 11303.5,-823.5 14303.5,-823.5 ; 11303.5,-223.5 14303.5,-223.5 ; 11304.5,370.5 14304.5,370.5 ; 12008.5,-1333.5 12008.5,-1133.5 ; 12008.5,7966.5 12008.5,8166.5 ; 12808.5,-1123.5 12808.5,-523.5 ; 14303.5,-523.5 11303.5,-523.5 ; 14303.5,76.5 11303.5,76.5 ; 14308.5,66.5 14308.5,-1133.5 ; 14308.5,871 11304.5,871 11303.5,871 11303.5,370.5 11303.5,76.5 ; 14308.5,1041.5 14508.5,1041.5 ; 14308.5,3416.5 14508.5,3416.5 ; 14308.5,5791.5 14508.5,5791.5 ; 11303.5,-523.5 11303.5,76.5 ; 14308.5,-1133.5 -291.5,-1133.5 -291.5,7966.5 14308.5,7966.5 14308.5,-1133.5 ; -491.5,-1333.5 14508.5,-1333.5 14508.5,8166.5 -491.5,8166.5 -491.5,-1333.5
  text "1" at 739.84,8036.5 h70
  text "2" at 3235.5,8036.5 h70
  text "3" at 5724.84,8036.5 h70
  text "4" at 8231.51,8036.5 h70
  text "5" at 10730.5,8036.5 h70
  text "6" at 13235.5,8036.5 h70
  text "A" at -416.5,6893.5 h70
  text "A" at 14383.5,6893.5 h70
  text "B" at -416.5,4513.5 h70
  text "B" at 14383.5,4513.5 h70
  text "C" at -416.5,2138.5 h70
  text "C" at 14383.5,2138.5 h70
  text "PROJECT TITLE:" at 11343.5,277.5 h45
  text ".PRJ_Title" at 11393.5,144.17 h70
  text "DESIGNED FOR:" at 11343.5,-23.5 h45
  text ".PRJ_Customer" at 11393.5,-163.5 h70
  text "D" at -416.5,-231.5 h70
  text "D" at 14383.5,-231.5 h70
  text "FILE NAME:" at 11343.5,-323.5 h45
  text ".PCB_File_Name_No_Path" at 11393.5,-443.5 h70
  text "Texas Instruments (TI) and/or its licensors do not warrant the accuracy or completeness of this specification" at 6374,-605.34 h45
  text "ENGINEER:" at 11343.5,-613.5 h45
  text "LAYOUT BY:" at 12848.5,-613.5 h45
  text "or any information contained therein. TI and/or its licensors do not warrant that this design will meet" at 6329.01,-718 h45
  text ".PRJ_Engineer" at 11393.5,-768.49 h70
  text ".PCB_Layout" at 12899,-768.49 h70
  text "the specifications, will be suitable for your application or fit for any particular purpose, or will operate in" at 6329.01,-830.67 h45
  text ".Layer_Name" at 577,-858.49 h60
  text "ALTIUM DESIGNER VERSION:" at 12848.5,-923.5 h45
  text "an implementation. TI and/or its licensors do not warrant that the design is production worthy. You should" at 6329.01,-943.33 h45
  text "completely validate and test your design implementation to confirm the system functionality for your application." at 6374,-1056 h45
  text ".print_Scale" at 11393.5,-1056.83 h70
  text ".Application_BuildNumber" at 12899,-1056.83 h70
  text "1" at 739.84,-1263.5 h70
  text "2" at 3235.5,-1263.5 h70
  text "3" at 5724.84,-1263.5 h70
  text "4" at 8231.51,-1263.5 h70
  text "5" at 10730.5,-1263.5 h70
  text "6" at 13235.5,-1263.5 h70
M10 Fab Notes:
  drawing of 189 lines, arcs and shapes, not listed
  text "DESIGN INFORMATION" at 12382.02,6356.17 h60
  text "MIN. TRACK WIDTH:" at 11737.46,6224.05 h60
  text "8" at 12833.7,6224.05 h60
  text "MIL" at 12988.46,6224.05 h60
  text "MIN. CLEARANCE:" at 11737.46,6099.92 h60
  text "0.2" at 12773.7,6099.93 h60
  text "mm" at 12988.46,6099.92 h60
  text "MIN. VIA PAD SIZE:" at 11737.46,5975.8 h60
  text "24" at 12803.71,5975.8 h60
  text "MIL" at 12988.46,5975.8 h60
  text "0.05mm (2MIL)" at 12432.46,5845.9 h60
  text "MINIMUM ANNULAR RING" at 11408.23,5837.67 h60
  text "EXTERNAL" at 13140.46,5837.67 h60
  text "PER" at 11608.23,5727.55 h60
  text "IPC-D-275 CLASS 2 LEVEL C" at 11828.23,5727.54 h60
  text "MIL, HOLES" at 13316.46,5627.07 h60
  text "+/-" at 12924,5618.48 h60
  text "+/-" at 13778,5618.48 h60
  text "REGISTRATION TOLERANCES:" at 11408.23,5617.42 h60
  text "METAL" at 12608,5617.42 h60
  text "5" at 13184.2,5617.42 h60
  text "3" at 14017.2,5617.42 h60
  text "MIL" at 14133.46,5617.42 h60
  text "HOLE SIZE TOLERANCE (UNLESS OTHERWISE SPECIFIED):" at 11408.23,5519.1 h60
  text "+/-" at 13778,5516.23 h60
  text "3" at 14017.2,5515.17 h60
  text "MIL" at 14133.46,5515.17 h60
  text "MATERIAL:" at 11333.46,5377.52 h60
  text "FR-4 High Tg" at 12319.9,5249 h60
  text "X" at 12175.46,5241.01 h60
  text "FR-408" at 11754.46,5236.49 h60
  text "OTHER" at 13242.46,5236.49 h60
  text "40.4 MIL (1.0mm) +/-10%" at 12074.56,5093.46 h60
  text "X" at 11955,5090 h60
  text "40MIL" at 13725,5086 h72
  text "THICKNESS:" at 11408.23,5085.24 h60
  text "OTHER" at 13359.46,5085.24 h60
  text "TOLERANCE:" at 11408.23,4946.92 h60
  text "X" at 12256.46,4946.92 h60
  text "ANSI IPC-6012 TYPE 3 CLASS 2" at 12434.48,4946.92 h60
  text "OTHER +/-" at 12434.46,4802.73 h60
  text "BOW & TWIST:" at 11408.23,4657.54 h60
  text "X" at 12256.46,4657.54 h60
  text "ANSI IPC-6012 TYPE 3 CLASS 2" at 12434.48,4657.54 h60
  text "OTHER +/-" at 12434.46,4510.85 h60
  text "DRILLING:" at 11333.46,4380.23 h60
  text "NC_DRILL FILES" at 13094.46,4275.04 h60
  text "REFERENCE:" at 11408.23,4271.1 h60
  text "X" at 12065.46,4271.01 h60
  text "AS SHOWN" at 12243.46,4271.1 h60
  text "X" at 12966.46,4271.1 h60
  text "OTHER" at 13392.46,4128.85 h60
  text "PTH COPPER THICKNESS:" at 11407.91,4125.32 h60
  text "X" at 12547.14,4125.32 h60
  text "20-30 um" at 12675.14,4125.32 h60
  text "BOARD FINISH:" at 11333.46,3977.73 h60
  text "SILKSCREEN:" at 11488.68,3867.6 h60
  text "X" at 12446.46,3867.6 h60
  text "TOP" at 12563.46,3867.6 h60
  text "X" at 12956.46,3867.6 h60
  text "BOTTOM" at 13074.46,3867.6 h60
  text "SILKSCREEN COLOR:" at 11488.68,3712.41 h60
  text "X" at 12445.46,3712.41 h60
  text "WHITE" at 12563.46,3712.41 h60
  text "OTHER" at 13074.46,3712.41 h60
  text "X" at 12576.46,3568.96 h60
  text "GREEN" at 12694.46,3568.96 h60
  text "OTHER" at 13312.46,3568.96 h60
  text "SOLDER RESIST COLOR:" at 11488.68,3562.1 h60
  text "X" at 12576.46,3414.71 h60
  text "MATTE" at 12694.46,3414.71 h60
  text "SEMI-GLOSS" at 13312,3414.07 h60
  text "IMMERSION GOLD (ENIG)" at 12394.46,3241.94 h60
  text "ENEPIG" at 13732,3234.72 h60
  text "SURFACE FINISH:" at 11333.46,3233.72 h60
  text "X" at 12216.46,3233.72 h60
  text "IMM. TIN/SILVER OR EQUIV" at 11663,3096.4 h60
  text "OTHER" at 13094.46,3092.47 h60
  text "ARRAY/PANEL:" at 11333.46,2937.09 h60
  text "CUT AND TRIM PER M1 BOARD OUTLINE" at 12394.46,2928.87 h60
  text "N.C. ROUTE" at 12394.46,2792.9 h60
  text "X" at 13082.46,2792.9 h60
  text "V. SCORE" at 13260.46,2792.9 h60
  text "CERTIFICATION:" at 11333.46,2663.77 h60
  text "MATERIALS AND WORKMANSHIP FOR ALL PCBS" at 12058.46,2663.77 h60
  text "TO MEET OR EXCEED THE REQUIREMENTS OF:" at 12058.46,2569.71 h60
  text "X" at 11695.97,2441.08 h60
  text "ANSI IPC-A-600F CLASS ->" at 11823.96,2441.08 h60
  text "X" at 13471.97,2441.08 h60
  text "2" at 13581.96,2441.08 h60
  text "1" at 13266.96,2439.58 h60
  text "3" at 13935.96,2439.58 h60
  text "X" at 12507.97,2293.39 h60
  text "RoHS" at 12635.96,2293.39 h60
  text "OTHER" at 13280.36,2293.39 h60
  text "PER ORDER" at 13677.42,2293.39 h60
  text "ALL BOARDS MUST MEET OR EXCEED UL94-V0 REQUIREMENTS." at 11361,2139.57 h60
  text "PCB MUST BEAR THE UL94V-0 UL REGISTERED MATERIAL ID NUMBER" at 11361,2023.5 h60
  text "ADDITIONAL REQUIREMENTS:" at 11333.46,1854.08 h60
  text "MICROSECTION:" at 11408.23,1746.95 h60
  text "YES" at 12313.96,1746.95 h60
  text "REQUIRED" at 13175.46,1602.62 h60
  text "BARE BOARD ELEC. TEST:" at 11408.23,1599.76 h60
  text "NONE" at 12713.96,1599.76 h60
  text "X" at 13057.46,1599.76 h60
  text "PER ORDER" at 13767.46,1599.76 h60
  text "XX MIL VIAS REQUIRE NON-CONDUCTIVE FILL AND PLANARIZE" at 11576.38,1394.82 h59
  text "XX MIL VIAS REQUIRE CONDUCTIVE FILL AND PLANARIZE" at 11584.38,1290.84 h60
  text "OUTER XX MIL VIAS REQUIRE 50 OHM SINGLE-ENDED IMPEDANCE" at 11583.39,1127.46 h58
  text "LAYER 2 & 3 (INNER LAYERS) XX MIL WIDE, XX MIL SPACE / TRACES REQUIRE 100 OHM DIFFERENTIAL IMPEDANCE" at 11575.39,891.74 h60
  text ".Layer_Name" at 577,-858.49 h60
M11 Gerber Information:
  lines w10: -292,-930.17 6308,-930.17 ; -292,-726.83 6310,-726.83 ; -292,-523.5 -292,-1133.5 3713,-1133.5 6310,-1133.5 6310,-523.5 -291.5,-523.5 -291.5,-1133.5 1284,-1133.5 ; 2173,-1133.5 2173,-523.5 ; 3440,-726.83 3440,-523.5 ; 4280,-726.83 4280,-523.5 ; 4902,-1140 4902,-937.17
  text "ALL ARTWORK VIEWED FROM TOP SIDE" at -228.5,-655.67 h60
  text "BOARD #:" at 2248,-655.67 h60
  text ".PRJ_Number" at 2793.5,-655.67 h60
  text "REV:" at 3638,-655.67 h60
  text ".PCB_Rev" at 3929.5,-655.67 h60
  text "SVN REV:" at 4476,-655.67 h60
  text ".VersionControl_RevNumber" at 4982,-655.67 h60
  text "LAYER NAME =" at -228.5,-858.49 h60
  text "TID #:" at 2248,-859 h60
  text ".TID" at 2793.5,-859 h60
  text "PLOT NAME =" at -228.5,-1064.34 h60
  text ".plot_File_Name" at 577,-1064.34 h60
  text "GENERATED    :" at 2250,-1064.34 h60
  text ".Print_Date" at 3119.5,-1064.34 h60
  text ".Print_Time" at 3848.5,-1064.34 h60
  text "TEXAS INSTRUMENTS" at 5113,-1064.34 h60
M12 Stackup:
  drawing of 295 lines, arcs and shapes, not listed
  text "Layer" at 9781.2,7840 h60
  text "Name" at 10191.11,7840 h60
  text "Material" at 11130.85,7840 h60
  text "Thickness" at 11990.62,7840 h60
  text "Constant" at 12640.46,7840 h60
  text "Board Layer Stack" at 13210.32,7840 h60
  text "1" at 9781.2,7720 h60
  text "Top Overlay" at 10191.11,7720 h60
  text "2" at 9781.2,7600 h60
  text "Top Solder" at 10191.11,7600 h60
  text "Solder Resist" at 11130.85,7600 h60
  text "0.40mil" at 11990.62,7600 h60
  text "3.5" at 12640.46,7600 h60
  text "3" at 9781.2,7480 h60
  text "Top Layer" at 10191.11,7480 h60
  text "Copper" at 11130.85,7480 h60
  text "1.40mil" at 11990.62,7480 h60
  text "4" at 9781.2,7360 h60
  text "Dielectric 1" at 10191.11,7360 h60
  text "FR-4" at 11130.85,7360 h60
  text "8.00mil" at 11990.62,7360 h60
  text "4.2" at 12640.46,7360 h60
  text "5" at 9781.2,7240 h60
  text "Signal Layer 1" at 10191.11,7240 h60
  text "Copper" at 11130.85,7240 h60
  text "1.40mil" at 11990.62,7240 h60
  text "6" at 9781.2,7120 h60
  text "Dielectric 2" at 10191.11,7120 h60
  text "FR-4" at 11130.85,7120 h60
  text "18.00mil" at 11990.62,7120 h60
  text "4.2" at 12640.46,7120 h60
  text "7" at 9781.2,7000 h60
  text "Signal Layer 2" at 10191.11,7000 h60
  text "Copper" at 11130.85,7000 h60
  text "1.40mil" at 11990.62,7000 h60
  text "8" at 9781.2,6880 h60
  text "Dielectric 3" at 10191.11,6880 h60
  text "FR-4" at 11130.85,6880 h60
  text "8.00mil" at 11990.62,6880 h60
  text "4.2" at 12640.46,6880 h60
  text "9" at 9781.2,6760 h60
  text "Bottom Layer" at 10191.11,6760 h60
  text "Copper" at 11130.85,6760 h60
  text "1.40mil" at 11990.62,6760 h60
  text "10" at 9781.2,6640 h60
  text "Bottom Solder" at 10191.11,6640 h60
  text "Solder Resist" at 11130.85,6640 h60
  text "0.40mil" at 11990.62,6640 h60
  text "3.5" at 12640.46,6640 h60
  text "11" at 9781.2,6520 h60
  text "Bottom Overlay" at 10191.11,6520 h60
  text ".Layer_Name" at 577,-858.49 h60
M13 Component Bodies Top:
  text ".Layer_Name" at 577,-858.49 h60
M14 Component Bodies Bottom:
  text ".Layer_Name" at 577,-858.49 h60
M15 Courtyards Top:
  text ".Layer_Name" at 577,-858.49 h60
M16 Courtyards Bottom:
  text ".Layer_Name" at 577,-858.49 h60
Drill Drawing:
  circle w10: c5363.72,3324.47 r16.58
  circle w10: c5363.72,3324.47 r27.63
  circle w10: c5363.72,3075.83 r27.63
  lines w10: 5336.09,2302.28 5336.09,2316.1 5349.9,2329.91 5336.09,2343.72 5336.09,2357.54 5349.9,2357.54 5363.72,2343.72 5377.53,2357.54 5391.34,2357.54 5391.34,2343.72 5377.53,2329.91 5391.34,2316.1 5391.34,2302.28 5377.53,2302.28 5363.72,2316.1 5349.9,2302.28 5336.09,2302.28 ; 5336.09,2481.86 5391.34,2481.86 5363.72,2426.6 5336.09,2481.86 ; 5336.09,2564.74 5349.9,2564.74 5349.9,2550.92 5377.53,2550.92 5377.53,2564.74 5391.34,2564.74 5391.34,2592.36 5377.53,2592.36 5377.53,2606.18 5349.9,2606.18 5349.9,2592.36 5336.09,2592.36 5336.09,2564.74 ; 5336.09,2689.06 5349.9,2689.06 5363.72,2675.24 5377.53,2689.06 5391.34,2689.06 5377.53,2702.87 5391.34,2716.68 5377.53,2716.68 5363.72,2730.5 5349.9,2716.68 5336.09,2716.68 5349.9,2702.87 5336.09,2689.06 ; 5336.09,2799.56 5391.34,2799.56 5391.34,2854.82 5336.09,2854.82 5336.09,2799.56 ; 5336.09,3186.34 5349.9,3186.34 5349.9,3172.52 5377.53,3172.52 5377.53,3186.34 5391.34,3186.34 5391.34,3213.96 5377.53,3213.96 5377.53,3227.78 5349.9,3227.78 5349.9,3213.96 5336.09,3213.96 5336.09,3186.34 ; 5336.09,3448.79 5363.72,3421.16 5391.34,3448.79 5363.72,3476.42 5336.09,3448.79 ; 5336.09,3669.8 5363.72,3683.62 5391.34,3669.8 5377.53,3697.43 5391.34,3725.06 5363.72,3711.24 5336.09,3725.06 5349.9,3697.43 5336.09,3669.8 ; 5347.14,3191.86 5355.43,3191.86 5355.43,3183.57 5372.01,3183.57 5372.01,3191.86 5380.29,3191.86 5380.29,3208.44 5372.01,3208.44 5372.01,3216.73 5355.43,3216.73 5355.43,3208.44 5347.14,3208.44 5347.14,3191.86 ; 5347.14,3680.85 5363.72,3689.14 5380.29,3680.85 5372.01,3697.43 5380.29,3714.01 5363.72,3705.72 5347.14,3714.01 5355.43,3697.43 5347.14,3680.85
  lines w12: 5286,2264.99 8517.49,2264.99 ; 5286,3881.15 8517.49,3881.15 ; 5623.86,2140.67 5623.86,4005.47 ; 5955.86,2140.67 5955.86,4005.47 ; 6592.43,2140.67 6592.43,4005.47 ; 6851.57,2140.67 6851.57,4005.47 ; 7226.72,2140.67 7226.72,4005.47 ; 7951.05,2140.67 7951.05,4005.47 ; 5286,2140.67 8517.49,2140.67 8517.49,4005.47 5286,4005.47 5286,2140.67
  text "Symbol" at 5360.59,3918.44 h72
  text "Quantity" at 5661.16,3918.44 h72
  text "Finished Hole Size" at 5993.16,3918.44 h72
  text "Plated" at 6629.72,3918.44 h72
  text "Hole Type" at 6888.86,3918.44 h72
  text "Drill Layer Pair" at 7264.02,3918.44 h72
  text "Hole Tolerance" at 7988.35,3918.44 h72
  text "5" at 5661.16,3794.12 h60
  text "7.87mil (0.200mm)" at 5993.16,3794.12 h60
  text "PTH" at 6629.72,3794.12 h60
  text "Round" at 6888.86,3794.12 h60
  text "Top Layer - Bottom Layer" at 7264.02,3794.12 h60
  text "D" at 5335.31,3784.13 h55.25
  text "92" at 5661.16,3669.8 h60
  text "11.81mil (0.300mm)" at 5993.16,3669.8 h60
  text "PTH" at 6629.72,3669.8 h60
  text "Round" at 6888.86,3669.8 h60
  text "Top Layer - Bottom Layer" at 7264.02,3669.8 h60
  text "2" at 5661.16,3545.48 h60
  text "25.59mil (0.650mm)" at 5993.16,3545.48 h60
  text "PTH" at 6629.72,3545.48 h60
  text "Round" at 6888.86,3545.48 h60
  text "Top Layer - Bottom Layer" at 7264.02,3545.48 h60
  text "C" at 5335.31,3535.49 h55.25
  text "6" at 5661.16,3421.16 h60
  text "33.47mil (0.850mm)" at 5993.16,3421.16 h60
  text "PTH" at 6629.72,3421.16 h60
  text "Round" at 6888.86,3421.16 h60
  text "Top Layer - Bottom Layer" at 7264.02,3421.16 h60
  text "8" at 5661.16,3296.84 h60
  text "35.43mil (0.900mm)" at 5993.16,3296.84 h60
  text "PTH" at 6629.72,3296.84 h60
  text "Round" at 6888.86,3296.84 h60
  text "Top Layer - Bottom Layer" at 7264.02,3296.84 h60
  text "1" at 5661.16,3172.52 h60
  text "39.37mil (1.000mm)" at 5993.16,3172.52 h60
  text "PTH" at 6629.72,3172.52 h60
  text "Round" at 6888.86,3172.52 h60
  text "Top Layer - Bottom Layer" at 7264.02,3172.52 h60
  text "3" at 5661.16,3048.2 h60
  text "40.00mil (1.016mm)" at 5993.16,3048.2 h60
  text "PTH" at 6629.72,3048.2 h60
  text "Round" at 6888.86,3048.2 h60
  text "Top Layer - Bottom Layer" at 7264.02,3048.2 h60
  text "4" at 5661.16,2923.88 h60
  text "41.34mil (1.050mm)" at 5993.16,2923.88 h60
  text "PTH" at 6629.72,2923.88 h60
  text "Round" at 6888.86,2923.88 h60
  text "Top Layer - Bottom Layer" at 7264.02,2923.88 h60
  text "A" at 5335.31,2913.89 h55.25
  text "8" at 5661.16,2799.56 h60
  text "49.21mil (1.250mm)" at 5993.16,2799.56 h60
  text "PTH" at 6629.72,2799.56 h60
  text "Round" at 6888.86,2799.56 h60
  text "Top Layer - Bottom Layer" at 7264.02,2799.56 h60
  text "4" at 5661.16,2675.24 h60
  text "53.15mil (1.350mm)" at 5993.16,2675.24 h60
  text "PTH" at 6629.72,2675.24 h60
  text "Round" at 6888.86,2675.24 h60
  text "Top Layer - Bottom Layer" at 7264.02,2675.24 h60
  text "5" at 5661.16,2550.92 h60
  text "63.00mil (1.600mm)" at 5993.16,2550.92 h60
  text "PTH" at 6629.72,2550.92 h60
  text "Round" at 6888.86,2550.92 h60
  text "Top Layer - Bottom Layer" at 7264.02,2550.92 h60
  text "2" at 5661.16,2426.6 h60
  text "100.00mil (2.540mm)" at 5993.16,2426.6 h60
  text "PTH" at 6629.72,2426.6 h60
  text "Round" at 6888.86,2426.6 h60
  text "Top Layer - Bottom Layer" at 7264.02,2426.6 h60
  text "4" at 5661.16,2302.28 h60
  text "125.00mil (3.175mm)" at 5993.16,2302.28 h60
  text "PTH" at 6629.72,2302.28 h60
  text "Round" at 6888.86,2302.28 h60
  text "Top Layer - Bottom Layer" at 7264.02,2302.28 h60
  text "144 Total" at 5661.16,2177.96 h60
  text ".Layer_Name" at 577,-858.49 h60
Mechanical 17:
  text ".Layer_Name" at 577,-858.49 h60
Mechanical 18:
  text ".Layer_Name" at 577,-858.49 h60
Mechanical 19:
  text ".Layer_Name" at 577,-858.49 h60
